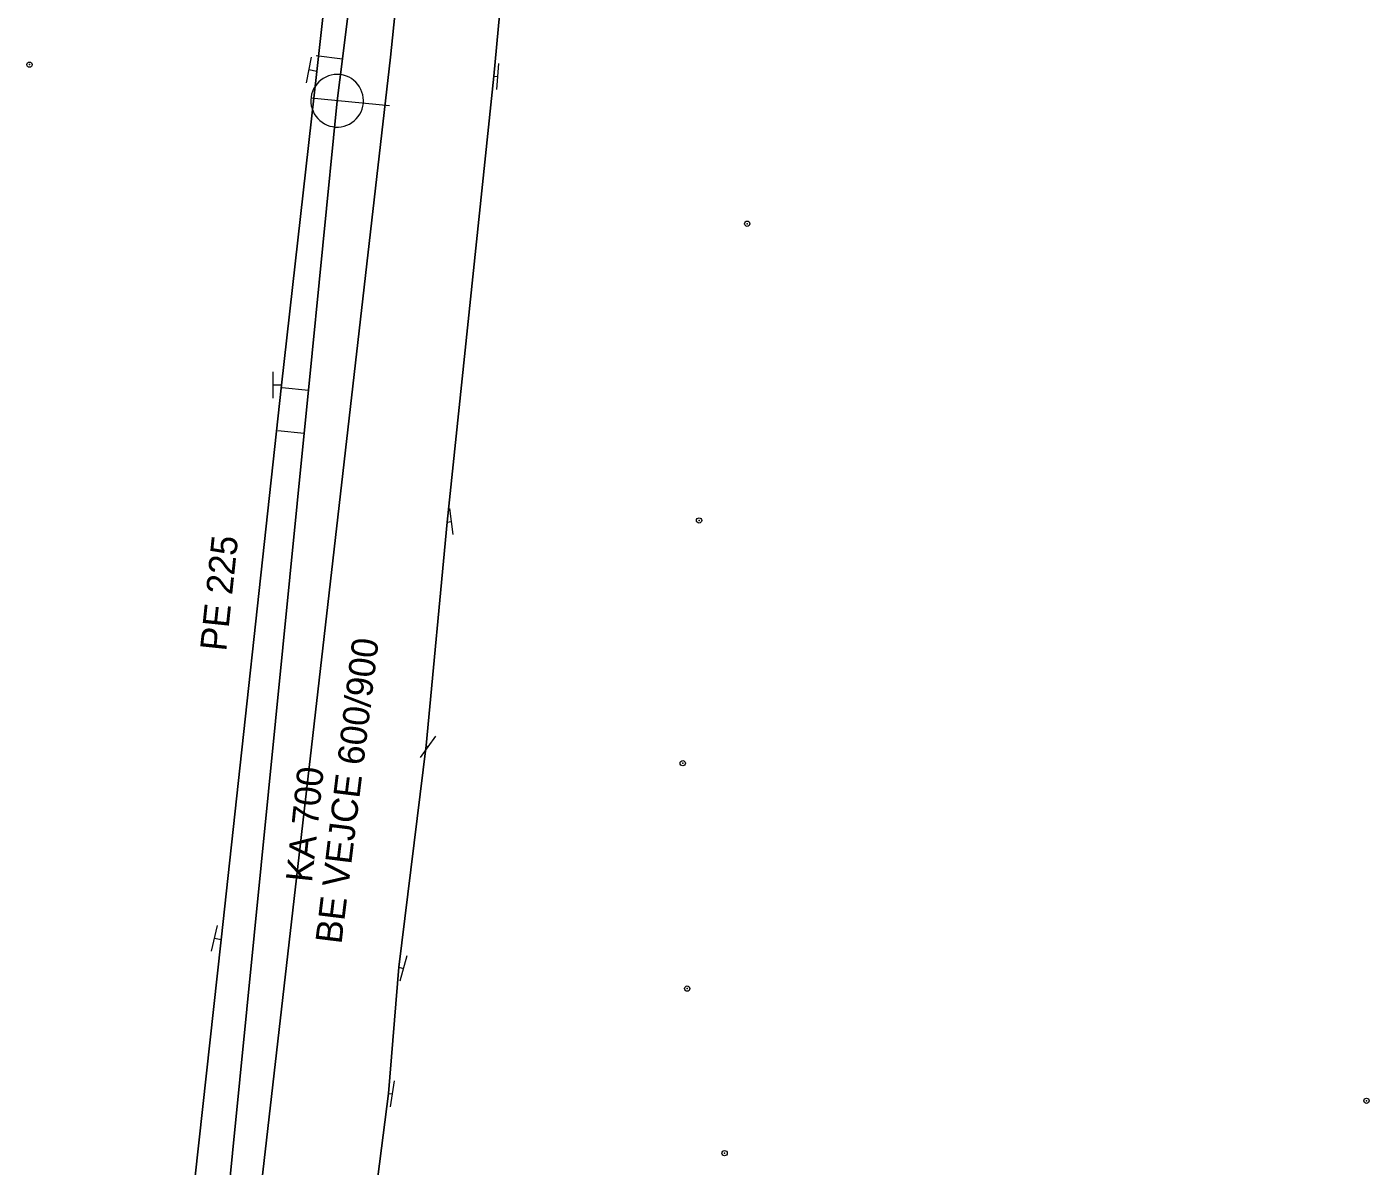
# Model space of a CAD drawing. Extents: x -783064 to -782702, y -1007904 to -1007145.
# Drawn here: x -782806.9 to -782755.9, y -1007555.7 to -1007512.4 of the extents above; entities that cross this region are included whole.
import ezdxf

# ---------------------------------------------------------------- set-up
doc = ezdxf.new("R2010")
doc.units = 0
doc.header["$LTSCALE"] = 0.4
doc.header["$PDMODE"] = 32
doc.header["$PDSIZE"] = 0.2
for name, color, linetype, lineweight in [('1', 7, 'Continuous', 13), ('11', 7, 'Continuous', 13), ('14', 7, 'Continuous', 13), ('17', 7, 'Continuous', 25), ('22', 7, 'Continuous', 13), ('34', 7, 'Continuous', 13)]:
    doc.layers.add(name, color=color, linetype=linetype, lineweight=lineweight)

msp = doc.modelspace()

# ---------------------------------------------------------------- linework, layer by layer
at = {"layer": '1'}
for p in [(-782806.809, -1007513.879), (-782779.539, -1007519.92), (-782781.37, -1007531.189), (-782781.989, -1007540.409), (-782781.82, -1007548.969), (-782756.01, -1007553.229), (-782780.399, -1007555.219)]:
    msp.add_point(p, dxfattribs=at)
at = {"layer": '11'}
for p, q in [((-782795.912, -1007513.528), (-782794.92, -1007513.652)), ((-782797.208, -1007526.138), (-782796.213, -1007526.237)), ((-782797.37, -1007527.77), (-782796.375, -1007527.869))]:
    msp.add_line(p, q, dxfattribs=at)
at = {"layer": '14'}
for p, q in [((-782795.89, -1007514.14), (-782796.19, -1007514.08)), ((-782789.17, -1007514.32), (-782789.03, -1007514.33)), ((-782797.23, -1007526.05), (-782797.55, -1007526.05)), ((-782790.94, -1007531.25), (-782790.789, -1007531.23)), ((-782791.739, -1007539.74), (-782791.67, -1007539.79)), ((-782799.52, -1007547.12), (-782799.78, -1007547.06)), ((-782792.78, -1007548.16), (-782792.6, -1007548.21)), ((-782793.17, -1007552.95), (-782793.03, -1007552.97))]:
    msp.add_line(p, q, dxfattribs=at)
at = {"layer": '14', "lineweight": 25}
for points in [[(-782795.12, -1007515.25), (-782794.92, -1007513.652), (-782793.776, -1007504.503), (-782791.037, -1007482.594), (-782789.989, -1007474.3)], [(-782798.949, -1007564.67), (-782793.087, -1007513.589), (-782789.92, -1007482.8)], [(-782800.399, -1007568.31), (-782800.135, -1007565.653), (-782799.905, -1007563.354), (-782796.375, -1007527.869), (-782796.213, -1007526.237), (-782795.12, -1007515.25)]]:
    msp.add_lwpolyline(points, dxfattribs=at)
at = {"layer": '17'}
for points in [[(-782784.199, -1007414.51), (-782788.17, -1007445.88), (-782789.899, -1007459.31), (-782791.09, -1007469.35), (-782793.219, -1007488.27), (-782794.285, -1007499.072), (-782794.78, -1007504.08), (-782795.89, -1007514.14), (-782797.23, -1007526.05), (-782799.52, -1007547.12), (-782801.219, -1007562.54)], [(-782794.527, -1007563.539), (-782793.17, -1007552.95), (-782792.78, -1007548.16), (-782791.739, -1007539.74), (-782790.94, -1007531.25), (-782789.17, -1007514.32), (-782788.309, -1007505.04), (-782787.02, -1007493.25), (-782786.27, -1007487.64), (-782784.98, -1007475.07), (-782783.55, -1007462.11), (-782782.149, -1007449.41), (-782782.032, -1007447.451), (-782779.226, -1007421.176)]]:
    msp.add_lwpolyline(points, dxfattribs=at)
at = {"layer": '22'}
msp.add_line((-782793.129, -1007515.448), (-782796.114, -1007515.151), dxfattribs=at)
msp.add_lwpolyline([(-782795.02, -1007514.254), (-782795.129, -1007514.25), (-782795.238, -1007514.257), (-782795.347, -1007514.276), (-782795.451, -1007514.306), (-782795.553, -1007514.348), (-782795.649, -1007514.401), (-782795.738, -1007514.464), (-782795.82, -1007514.537), (-782795.894, -1007514.618), (-782795.958, -1007514.706), (-782796.013, -1007514.801), (-782796.056, -1007514.902), (-782796.089, -1007515.006), (-782796.109, -1007515.114), (-782796.118, -1007515.223), (-782796.115, -1007515.332), (-782796.101, -1007515.441), (-782796.074, -1007515.547), (-782796.035, -1007515.65), (-782795.987, -1007515.747), (-782795.926, -1007515.84), (-782795.857, -1007515.924), (-782795.779, -1007516.001), (-782795.693, -1007516.069), (-782795.6, -1007516.126), (-782795.501, -1007516.173), (-782795.397, -1007516.21), (-782795.291, -1007516.234), (-782795.182, -1007516.247), (-782795.073, -1007516.248), (-782794.964, -1007516.238), (-782794.857, -1007516.214), (-782794.753, -1007516.18), (-782794.653, -1007516.135), (-782794.559, -1007516.078), (-782794.472, -1007516.012), (-782794.392, -1007515.937), (-782794.322, -1007515.853), (-782794.261, -1007515.763), (-782794.21, -1007515.666), (-782794.169, -1007515.564), (-782794.141, -1007515.458), (-782794.124, -1007515.35), (-782794.119, -1007515.24), (-782794.126, -1007515.131), (-782794.145, -1007515.024), (-782794.176, -1007514.918), (-782794.218, -1007514.817), (-782794.271, -1007514.721), (-782794.333, -1007514.631), (-782794.405, -1007514.549), (-782794.486, -1007514.475), (-782794.574, -1007514.41), (-782794.669, -1007514.357), (-782794.77, -1007514.313), (-782794.875, -1007514.28), (-782794.982, -1007514.259)], close=True, dxfattribs=at)
at = {"layer": '34'}
for p, q in [((-782796.287, -1007514.57), (-782796.091, -1007513.589)), ((-782788.994, -1007513.831), (-782789.066, -1007514.828)), ((-782797.549, -1007526.55), (-782797.549, -1007525.55)), ((-782790.855, -1007530.734), (-782790.723, -1007531.725)), ((-782791.379, -1007539.382), (-782791.961, -1007540.196)), ((-782799.891, -1007547.547), (-782799.667, -1007546.572)), ((-782792.466, -1007547.728), (-782792.734, -1007548.691)), ((-782792.959, -1007552.474), (-782793.101, -1007553.464))]:
    msp.add_line(p, q, dxfattribs=at)

# ---------------------------------------------------------------- texts
at = {"layer": '1'}
for s, rotation, p in [('PE 225', 84, (-782799.336, -1007536.18)), ('BE VEJCE 600/900', 83, (-782794.958, -1007547.303)), ('KA 700', 84, (-782796.08, -1007544.961))]:
    msp.add_text(s, height=1, rotation=rotation, dxfattribs=at).set_placement(p)

doc.saveas('drawing.dxf')
